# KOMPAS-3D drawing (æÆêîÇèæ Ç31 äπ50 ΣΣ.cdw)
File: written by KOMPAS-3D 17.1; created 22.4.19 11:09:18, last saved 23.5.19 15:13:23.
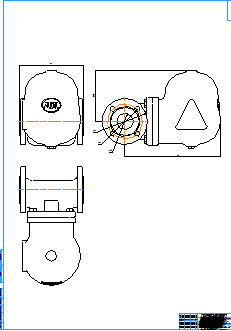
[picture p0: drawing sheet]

Sheet 1: A0, portrait

Title block, sheet 1: name: СТИМАКС А31 Ду50 ф/ф; material: Внимание! Данный продукт является объектом авторского права ООО «Торговый Дом АДЛ». / Запрещается изменение, копирование, распространение / (в том числе путем копирования на другие сайты и ресурсы в Интернете) / или любое иное использование информации и объектов без предварительного / согласия правообладателя (ООО «Торговый Дом АДЛ»).; mass: 35; sheets: 1; organisation: ООО "Торговый дом АДЛ"; sheet format: A0; stored path: \\adlc.lan\data\АДЛ_ПКД\3D-модели\ADL production\Конденсатоотводчики СТИМАКС\Поплавковые\Серия А31\KOMPAS 2D\СТИМАКС А31 Ду50 фф.cdw

Views: Вид 1, Проекционный вид 2, Проекционный вид 3
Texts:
  user
Dimensions and other numbers on the sheet: 230; 343; 181; 59; 125; 165; 1:1; 1; 35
